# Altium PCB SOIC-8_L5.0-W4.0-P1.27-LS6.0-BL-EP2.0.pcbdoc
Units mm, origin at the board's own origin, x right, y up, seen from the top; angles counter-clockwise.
Board outline 18.02 x 20.28 mm, 2 copper layers (Top Layer, Bottom Layer), stack 0 mm thick; 1 components, 0 nets, 9 pads, 4 vias.
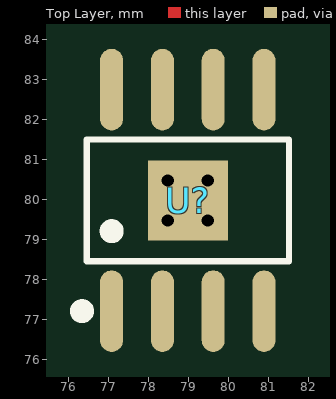
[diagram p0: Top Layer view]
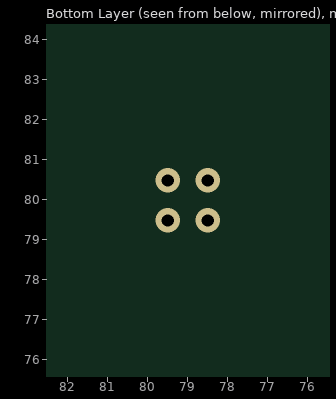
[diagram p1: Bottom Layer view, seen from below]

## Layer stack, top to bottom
Top Layer: signal copper (thickness not stored)
Bottom Layer: signal copper (thickness not stored)

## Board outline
87.871,69.85 69.85,69.85 69.85,90.126 87.871,90.126

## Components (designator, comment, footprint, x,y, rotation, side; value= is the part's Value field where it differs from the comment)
U? "" SOIC-8_L5.0-W4.0-P1.27-LS6.0-BL-EP2.0 78.995,79.988 r0 top

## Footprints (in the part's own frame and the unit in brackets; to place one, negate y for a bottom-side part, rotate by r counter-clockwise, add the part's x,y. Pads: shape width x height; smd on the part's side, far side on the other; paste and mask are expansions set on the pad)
SOIC-8_L5.0-W4.0-P1.27-LS6.0-BL-EP2.0 [mm]
  oval 0.574x2.038 smd: 1(-1.905,-2.769) 2(-0.635,-2.769) 3(0.635,-2.769) 4(1.905,-2.769) 5(1.905,2.769) 6(0.635,2.769) 7(-0.635,2.769) 8(-1.905,2.769)
  rect 2x2 smd: 9(0,0)
  silkscreen extent -2.79,-2.92 2.53,1.52

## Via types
v1: diameter 0.61, hole 0.305, Top Layer to Bottom Layer, 4 vias

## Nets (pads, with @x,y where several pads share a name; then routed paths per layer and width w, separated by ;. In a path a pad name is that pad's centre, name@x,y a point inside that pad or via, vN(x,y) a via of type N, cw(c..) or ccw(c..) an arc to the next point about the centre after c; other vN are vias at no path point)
pads on no net: U?.1 U?.2 U?.3 U?.4 U?.5 U?.6 U?.7 U?.8 U?.9
copper on no net:
  other v1: 78.495,79.488 79.495,79.488 78.495,80.488 79.495,80.488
